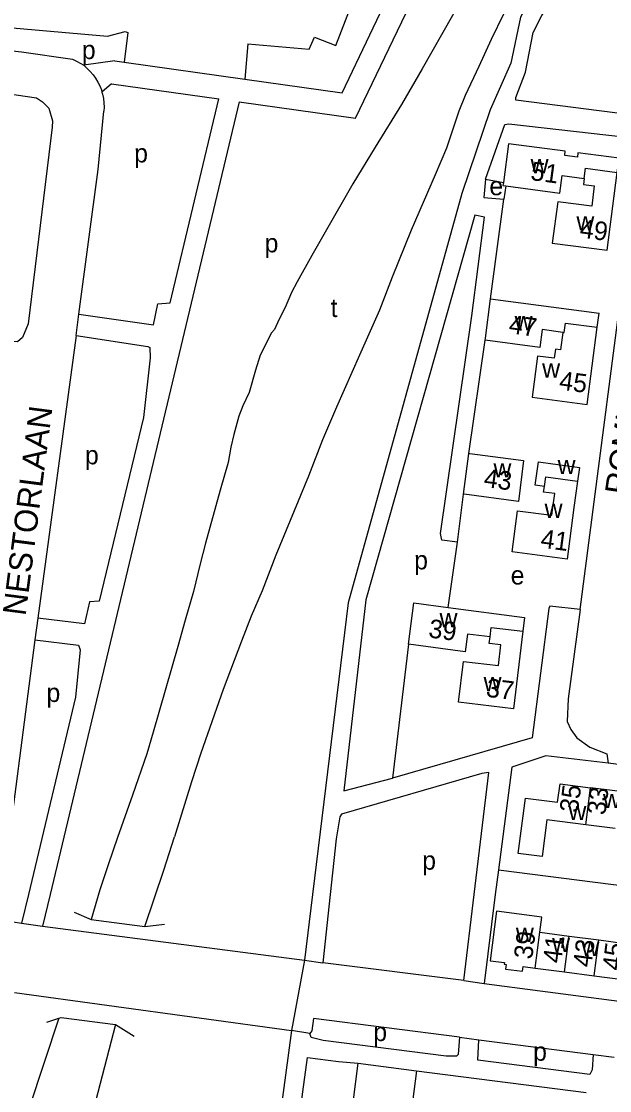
# Model space of a CAD drawing. Extents: x 161773 to 163836, y 384796 to 386521.
# Drawn here: x 162246.8 to 162373.5, y 386124.5 to 386354.7 of the extents above; entities that cross this region are included whole.
import ezdxf

# ---------------------------------------------------------------- set-up
doc = ezdxf.new("R2010")
doc.units = 0
for name, color, linetype in [('BLT_Basislijn', 7, 'Continuous'), ('BLT_Bebouwing', 7, 'Continuous'), ('BLT_Centroide', 7, 'Continuous'), ('BLT_Huisnummer', 7, 'Continuous'), ('BLT_Huisnummer_ tussenligend', 7, 'Continuous'), ('BLT_Onderverdeling_panden', 7, 'Continuous'), ('BLT_Straatnaam', 7, 'Continuous'), ('BLT_Vlakafsluiter', 7, 'Continuous')]:
    doc.layers.add(name, color=color, linetype=linetype)

msp = doc.modelspace()

# ---------------------------------------------------------------- linework, layer by layer
at = {"layer": 'BLT_Basislijn'}
for p, q in [((162295.54, 386349.82), (162294.9, 386342.25)), ((162266.9, 386346.2), (162260.21, 386345.22)), ((162266.9, 386346.2), (162268.92, 386345.92)), ((162268.92, 386345.92), (162294.9, 386342.25)), ((162266.2, 386341.25), (162264.15, 386339.45)), ((162266.2, 386341.25), (162289.29, 386337.99)), ((162367.14, 386228.05), (162380.3, 386329.37)), ((162346.75, 386320.71), (162350.61, 386320.01)), ((162351.13, 386319.25), (162350.72, 386316.38)), ((162347.86, 386294.92), (162350.72, 386316.38)), ((162258.55, 386287.04), (162259.18, 386291.62)), ((162258.55, 386287.04), (162250.35, 386226.18)), ((162343.14, 386261.65), (162346.68, 386286.06)), ((162340.74, 386242.55), (162342.02, 386252.9)), ((162338.7, 386228.49), (162340.74, 386242.55)), ((162250.35, 386226.18), (162249.71, 386221.49)), ((162330.17, 386220.55), (162326.76, 386191.75)), ((162258.17, 386162.86), (162261.83, 386161.28)), ((162246.83, 386160.49), (162251.35, 386159.86)), ((162261.83, 386161.28), (162273.37, 386159.82)), ((162273.37, 386159.82), (162277.65, 386160.27)), ((162251.35, 386159.86), (162307.77, 386152.54)), ((162307.77, 386152.54), (162311.74, 386151.99)), ((162342.07, 386148.13), (162311.74, 386151.99)), ((162342.07, 386148.13), (162346.48, 386147.55)), ((162252.28, 386139.22), (162254.86, 386140.04)), ((162267.07, 386138.67), (162271.06, 386136.18)), ((162304.99, 386137.39), (162296.29, 386072.34)), ((162308.92, 386136.72), (162304.99, 386137.39)), ((162341.19, 386135.96), (162345.36, 386135.41)), ((162345.36, 386135.41), (162369.94, 386132.24)), ((162315.12, 386130.72), (162319.36, 386130.34)), ((162369.94, 386132.24), (162374.45, 386131.66)), ((162331.91, 386128.71), (162368.44, 386124.01))]:
    msp.add_line(p, q, dxfattribs=at)
for points in [[(162407.38, 386445.51), (162405.6, 386437.8), (162403.77, 386432.07), (162398.04, 386420.29), (162360.61, 386365.02), (162356.09, 386358.8), (162354.27, 386355.61), (162352.21, 386345.65), (162347.75, 386335.62), (162341.7, 386317.64), (162317.21, 386229.49), (162309.5, 386166.67), (162307.77, 386152.54)], [(162294.9, 386342.25), (162315.86, 386339.29), (162327.83, 386364.37), (162345.54, 386397.61), (162349.61, 386406.73), (162352.1, 386415.54), (162353.69, 386428.11), (162355.54, 386434.28)], [(162293.67, 386337.37), (162318.79, 386333.82), (162332.3, 386362.12), (162350.03, 386395.42), (162354.32, 386405.02), (162357.01, 386414.54), (162358.6, 386427.07), (162360.33, 386432.85)], [(162295.54, 386349.82), (162308.76, 386348.71), (162309.95, 386351.3), (162314.5, 386349.45), (162330.46, 386390.74), (162334.64, 386432.77)], [(162380.79, 386334.16), (162353.27, 386337.73), (162353.27, 386338.3), (162355.39, 386343.74), (162357.06, 386352.3), (162358.89, 386355.93), (162381.65, 386390.69), (162387.83, 386399.42)], [(162353.9, 386391.69), (162344.94, 386369.64), (162343.2, 386365.62), (162341.65, 386360.13), (162340.46, 386357.48), (162339.63, 386355.92), (162333.14, 386344.49)], [(162350.61, 386356.2), (162347.95, 386350.8), (162345.3, 386344.95)], [(162233.3, 386354.28), (162265.36, 386351.49), (162269.14, 386352.49), (162269.74, 386352.29), (162268.92, 386345.92)], [(162228.95, 386350.1), (162246.84, 386348.11), (162257.79, 386346.51)], [(162257.79, 386346.51), (162258.64, 386346.12), (162259.46, 386345.66), (162260.21, 386345.22)], [(162260.21, 386345.22), (162260.95, 386344.54), (162261.62, 386343.88), (162262.23, 386343.17), (162262.78, 386342.42), (162263.27, 386341.61), (162263.68, 386340.77), (162264.02, 386339.9), (162264.15, 386339.45)], [(162333.14, 386344.49), (162328.66, 386336.8), (162322.99, 386327.57), (162318.15, 386319.7), (162312.21, 386309.27)], [(162345.3, 386344.95), (162342.38, 386338.73), (162341.01, 386335.34), (162338.35, 386327.38), (162335.89, 386321.62), (162330.77, 386309.73)], [(162226.68, 386341.63), (162227.56, 386341.53), (162250.01, 386338.22), (162251.35, 386337.36), (162252.67, 386335.96), (162253.5, 386333.29), (162253.45, 386331.89), (162248.27, 386289.55), (162247.01, 386286.61), (162245.96, 386285.7), (162239.56, 386286.16)], [(162293.67, 386337.37), (162252.97, 386166.67), (162251.35, 386159.86)], [(162259.18, 386291.62), (162275.25, 386289.36), (162276.18, 386293.85), (162278.84, 386294.09), (162289.29, 386337.99)], [(162264.15, 386339.45), (162264.28, 386339), (162264.47, 386338.08), (162264.58, 386337.15), (162264.6, 386336.22), (162264.56, 386335.36)], [(162259.18, 386291.62), (162263.3, 386322.76), (162264.56, 386335.36)], [(162346.75, 386320.71), (162350.93, 386332.44), (162351.82, 386332.63), (162380.3, 386329.37)], [(162346.75, 386320.71), (162346.42, 386316.72), (162350.72, 386316.38)], [(162340.74, 386242.55), (162337.35, 386242.97), (162337.09, 386244.4), (162343.83, 386291.27), (162346.57, 386312.55), (162344.47, 386312.93), (162321.01, 386230.11), (162316.28, 386189.02), (162326.76, 386191.75)], [(162330.77, 386309.73), (162326.65, 386299.58), (162323.91, 386292.53), (162319.61, 386282.84), (162314.68, 386271.59), (162311.66, 386264.55), (162308.64, 386256.77)], [(162312.21, 386309.27), (162309.37, 386304.24), (162306.17, 386298.57), (162304.98, 386296.28), (162303.61, 386293.08), (162302.24, 386290.43), (162301.33, 386288.33), (162300.69, 386287.6), (162298.22, 386282.84), (162297.21, 386279.55), (162295.84, 386274.79), (162294.47, 386271.86), (162293.65, 386269.67), (162292.55, 386265.73), (162291.91, 386262.99), (162291.36, 386259.7)], [(162258.55, 386287.04), (162274.04, 386284.65), (162274.44, 386284.46), (162274.54, 386282.23), (162273.11, 386269.35), (162263.51, 386229.87), (162261.46, 386229.71), (162260.41, 386224.96), (162250.35, 386226.18)], [(162291.36, 386259.7), (162289.62, 386253.75), (162286.43, 386242.32), (162285.33, 386237.84), (162283.87, 386231.89), (162282.04, 386225.76), (162280.48, 386220.09)], [(162308.64, 386256.77), (162301.6, 386239.76), (162298.68, 386232.07), (162296.3, 386226.59), (162294.2, 386221.19)], [(162367.14, 386228.05), (162360.64, 386228.77), (162360.42, 386228.29), (162356.82, 386200.44), (162326.76, 386191.75)], [(162367.14, 386228.05), (162364.54, 386208.78), (162364.35, 386203.94), (162365.12, 386202.2), (162366.47, 386200.39), (162369.23, 386198.37), (162372.89, 386197), (162373.17, 386194.96)], [(162249.71, 386221.49), (162242.57, 386166.67), (162242.23, 386164.06), (162244.14, 386161.26), (162245.01, 386160.77), (162246.83, 386160.49)], [(162249.71, 386221.49), (162259.1, 386220.34), (162259.46, 386219.38), (162258.46, 386209.16), (162248.31, 386166.67), (162246.83, 386160.49)], [(162280.48, 386220.09), (162275.18, 386201.61), (162273.81, 386196.95), (162270.7, 386188.08), (162267.5, 386178.93)], [(162294.2, 386221.19), (162290.27, 386210.85), (162285.42, 386197.13), (162283.41, 386190.91), (162279.75, 386179.11)], [(162373.17, 386194.96), (162359.78, 386196.56), (162352.41, 386194.06), (162349.54, 386172.01)], [(162485.66, 386180.43), (162484.59, 386180.57), (162373.17, 386194.96)], [(162342.07, 386148.13), (162344.32, 386166.67), (162347.49, 386192.93), (162345.97, 386192.73), (162315.76, 386183.95), (162315.38, 386183.39), (162314.62, 386178.69), (162313.32, 386166.67), (162311.74, 386151.99)], [(162267.5, 386178.93), (162265.49, 386173.08), (162263.66, 386167.68), (162261.83, 386161.28)], [(162273.37, 386159.82), (162277.46, 386171.89), (162279.75, 386179.11)], [(162349.54, 386172.01), (162348.88, 386166.67), (162346.48, 386147.55)], [(162349.54, 386172.01), (162391.2, 386166.67), (162413.94, 386163.45)], [(162346.48, 386147.55), (162478.17, 386130.31), (162479.16, 386130.19)], [(162245.3, 386145.55), (162304.99, 386137.39)], [(162254.86, 386140.04), (162248.46, 386120.76), (162246.78, 386114.69), (162245.11, 386108.63)], [(162254.86, 386140.04), (162255.33, 386140.18), (162267.07, 386138.67)], [(162341.19, 386135.96), (162309.72, 386140), (162309.32, 386137.3), (162308.92, 386136.72)], [(162267.07, 386138.67), (162261.82, 386118.49), (162258.26, 386104.86)], [(162341.19, 386135.96), (162340.85, 386132.26), (162340.54, 386131.88), (162338.31, 386131.88), (162311.76, 386135.27), (162309.2, 386135.88), (162308.92, 386136.72)], [(162369.94, 386132.24), (162369.75, 386128.94), (162369.23, 386127.93), (162345.08, 386131.04), (162345.36, 386135.41)], [(162300.43, 386071.84), (162303.21, 386093.04), (162308.45, 386131.55), (162315.12, 386130.72)]]:
    msp.add_lwpolyline(points, dxfattribs=at)
at = {"layer": 'BLT_Bebouwing'}
for p, q in [((162342.02, 386252.9), (162343.14, 386261.65)), ((162343.14, 386261.65), (162343.37, 386261.62)), ((162342.18, 386252.88), (162342.02, 386252.9)), ((162375.77, 386188.82), (162369.41, 386189.65)), ((162374.73, 386180.89), (162368.37, 386181.71)), ((162358.46, 386158.54), (162364.77, 386157.72)), ((162364.77, 386157.72), (162371.15, 386156.89)), ((162371.15, 386156.89), (162377.35, 386156.08)), ((162357.46, 386150.82), (162363.76, 386150)), ((162363.76, 386150), (162370.14, 386149.17)), ((162370.14, 386149.17), (162376.34, 386148.36)), ((162319.36, 386130.34), (162331.91, 386128.71))]:
    msp.add_line(p, q, dxfattribs=at)
for points in [[(162366.57, 386325.47), (162363.83, 386325.82), (162363.95, 386326.71), (162351.71, 386328.33), (162350.61, 386320.01)], [(162375.12, 386322.16), (162375.53, 386325.21), (162366.69, 386326.36), (162366.57, 386325.47)], [(162351.13, 386319.25), (162362.76, 386317.71), (162363.25, 386321.47), (162368.02, 386320.85)], [(162368.02, 386320.85), (162367.85, 386319.56), (162370.21, 386319.25), (162369.64, 386314.88), (162362.32, 386315.83), (162361.15, 386306.92), (162372.97, 386305.38), (162375.12, 386322.16)], [(162350.61, 386320.01), (162350.52, 386319.33), (162351.13, 386319.25)], [(162346.68, 386286.06), (162346.76, 386286.48), (162347.86, 386294.92)], [(162347.86, 386294.92), (162371.25, 386291.88)], [(162370.85, 386288.82), (162371.25, 386291.88)], [(162363.43, 386287.72), (162358.98, 386288.3), (162358.44, 386284.45), (162346.68, 386286.06)], [(162363.43, 386287.72), (162362.95, 386283.97), (162361.83, 386284.11), (162361.57, 386282.13), (162358, 386282.6), (162356.85, 386273.73), (162368.69, 386272.19), (162370.85, 386288.82)], [(162343.37, 386261.62), (162354.97, 386260.14), (162353.84, 386251.28), (162342.18, 386252.88)], [(162359.46, 386254.53), (162357.49, 386254.79), (162358.16, 386259.82), (162366.98, 386258.64), (162366.58, 386255.68)], [(162365.82, 386250), (162364.33, 386238.87), (162352.51, 386240.45), (162353.69, 386249.31), (162361.05, 386248.33), (162361.27, 386250), (162361.67, 386252.99), (162359.29, 386253.31), (162359.46, 386254.53)], [(162366.58, 386255.68), (162365.82, 386250)], [(162330.17, 386220.55), (162331.35, 386229.46), (162338.7, 386228.49)], [(162338.7, 386228.49), (162355.17, 386226.32), (162354.81, 386223.38)], [(162342.89, 386222.76), (162342.39, 386218.94), (162330.17, 386220.55)], [(162354.81, 386223.38), (162352.81, 386206.66), (162340.96, 386208.09)], [(162340.96, 386208.09), (162342.02, 386216.87), (162347.05, 386216.27), (162349.53, 386215.97), (162350.07, 386220.45), (162347.59, 386220.75), (162347.76, 386222.17)], [(162347.76, 386222.17), (162342.89, 386222.76)], [(162368.37, 386181.71), (162359.97, 386182.79), (162358.94, 386174.87), (162353.8, 386175.54), (162355.35, 386187.44), (162362.3, 386186.54), (162362.82, 386190.51), (162369.41, 386189.65)], [(162358.46, 386158.54), (162358.89, 386161.79), (162349.14, 386163.06), (162347.75, 386152.41), (162350.85, 386152.01), (162350.81, 386151.68), (162351.23, 386151.63), (162351.1, 386150.63), (162354.74, 386150.16), (162354.87, 386151.15), (162357.46, 386150.82)], [(162317.14, 386113.1), (162317.18, 386113.41), (162319.36, 386130.34)], [(162331.91, 386128.71), (162330.77, 386119.84), (162330.58, 386119.86), (162329.92, 386114.76), (162342.33, 386113.16), (162342.17, 386111.98)]]:
    msp.add_lwpolyline(points, dxfattribs=at)
at = {"layer": 'BLT_Onderverdeling_panden'}
for p, q in [((162368.37, 386181.71), (162369.41, 386189.65)), ((162357.46, 386150.82), (162358.46, 386158.54)), ((162363.76, 386150), (162364.77, 386157.72)), ((162370.14, 386149.17), (162371.15, 386156.89))]:
    msp.add_line(p, q, dxfattribs=at)
for points in [[(162368.02, 386320.85), (162368.3, 386323.04), (162375.12, 386322.16)], [(162363.43, 386287.72), (162363.72, 386287.68), (162363.99, 386289.72), (162370.85, 386288.82)], [(162359.46, 386254.53), (162359.74, 386256.61), (162366.58, 386255.68)], [(162347.76, 386222.17), (162348, 386224.2), (162354.81, 386223.38)]]:
    msp.add_lwpolyline(points, dxfattribs=at)
at = {"layer": 'BLT_Vlakafsluiter'}
msp.add_line((162307.77, 386152.54), (162304.99, 386137.39), dxfattribs=at)

# ---------------------------------------------------------------- texts
at = {"layer": 'BLT_Centroide'}
for s, p in [('p', (162259.81, 386346.55)), ('p', (162271.08, 386324.3)), ('w', (162356.48, 386321.96)), ('e', (162347.6, 386317.24)), ('w', (162366.35, 386309.66)), ('p', (162299.18, 386304.94)), ('t', (162313.4, 386291.01)), ('w', (162353.04, 386288.16)), ('w', (162358.97, 386277.95)), ('p', (162260.48, 386259.3)), ('w', (162348.48, 386256.47)), ('w', (162362.3, 386257.19)), ('w', (162359.5, 386247.75)), ('p', (162331.4, 386236.68)), ('e', (162352.19, 386233.42)), ('w', (162336.87, 386224.19)), ('w', (162346.36, 386210.44)), ('p', (162252.19, 386208.13)), ('w', (162372.06, 386185.28)), ('w', (162364.64, 386182.69)), ('p', (162333.13, 386172.02)), ('w', (162353.31, 386156.44)), ('w', (162361.11, 386154.27)), ('w', (162367.45, 386153.44)), ('p', (162322.59, 386135.11)), ('p', (162357.02, 386130.88))]:
    msp.add_text(s, height=4, dxfattribs=at).set_placement(p)
at = {"layer": 'BLT_Huisnummer'}
for s, rotation, p in [('51', 352.4397, (162356.33, 386320.54)), ('49', 352.5429, (162366.94, 386308.17)), ('47', 352.1832, (162351.64, 386287.55)), ('45', 352.5744, (162362.49, 386275.44)), ('43', 352.1864, (162346.26, 386254.47)), ('41', 352.3746, (162358.48, 386241.4)), ('39', 352.4852, (162334.35, 386222.05)), ('37', 353.1538, (162346.76, 386209.27)), ('35', 82.6637, (162366.66, 386184.16)), ('39', 82.5857, (162356.8, 386152.61)), ('43', 82.5848, (162369.55, 386150.88))]:
    msp.add_text(s, height=4, rotation=rotation, dxfattribs=at).set_placement(p)
at = {"layer": 'BLT_Huisnummer_ tussenligend'}
for s, rotation, p in [('33', 82.6628, (162372.56, 386183.66)), ('41', 82.5857, (162363.05, 386151.75)), ('45', 82.5848, (162375.87, 386150.17))]:
    msp.add_text(s, height=4, rotation=rotation, dxfattribs=at).set_placement(p)
at = {"layer": 'BLT_Straatnaam'}
for s, height, rotation, p in [('ROMULUSLAAN', 4.9999, 81.7288, (162377.4, 386252.52)), ('NESTORLAAN', 5, 82.6507, (162247.69, 386226.55))]:
    msp.add_text(s, height=height, rotation=rotation, dxfattribs=at).set_placement(p)

doc.saveas('drawing.dxf')
